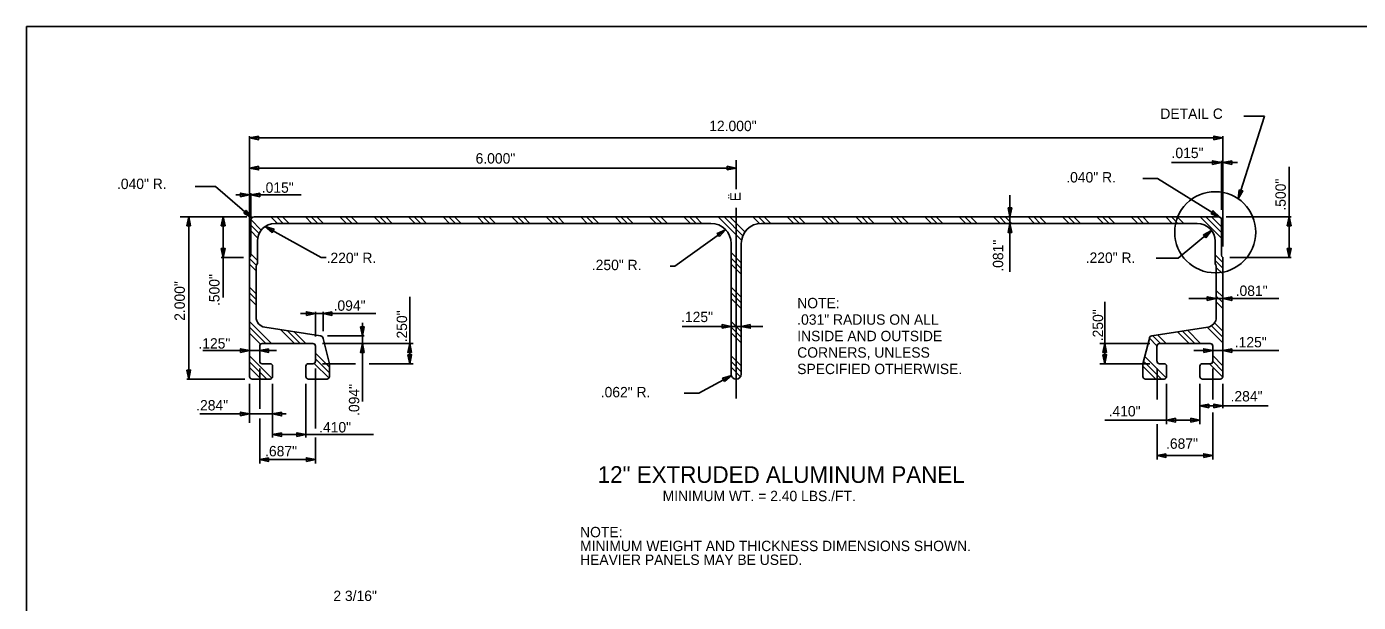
# Model space of a CAD drawing. Extents: x -439.1 to -407.9, y -458.1 to -437.7.
# Drawn here: x -439.11 to -419.86, y -446 to -437.68 of the extents above; entities that cross this region are included whole.
import ezdxf

# ---------------------------------------------------------------- set-up
doc = ezdxf.new("R2010")
doc.units = 0
for name, color, linetype in [('Draft_Named_Boundary', 7, 'Continuous'), ('Level 4', 7, 'Continuous'), ('Level 45', 7, 'Continuous')]:
    doc.layers.add(name, color=color, linetype=linetype)

msp = doc.modelspace()

# ---------------------------------------------------------------- linework, layer by layer
at = {"layer": 'Draft_Named_Boundary'}
msp.add_lwpolyline([(-439.109, -458.051), (-407.859, -458.051), (-407.859, -437.676), (-439.109, -437.676)], close=True, dxfattribs=at)
at = {"layer": 'Level 4'}
for p, q in [((-421.595, -440.165), (-421.215, -438.972)), ((-421.513, -438.972), (-421.215, -438.972)), ((-435.887, -441.017), (-435.887, -439.257)), ((-421.817, -439.284), (-435.887, -439.284)), ((-421.817, -440.855), (-421.817, -439.257)), ((-428.852, -440.024), (-428.852, -439.604)), ((-422.559, -439.641), (-421.608, -439.641)), ((-421.835, -440.322), (-421.835, -439.614)), ((-435.887, -439.72), (-428.852, -439.72)), ((-422.763, -439.87), (-422.972, -439.87)), ((-421.863, -440.428), (-422.763, -439.87)), ((-420.859, -439.7), (-420.859, -440.424)), ((-436.671, -439.984), (-436.378, -439.984)), ((-435.856, -440.439), (-436.378, -439.984)), ((-436.085, -440.107), (-435.143, -440.107)), ((-435.869, -440.431), (-435.869, -440.081)), ((-424.895, -441.218), (-424.895, -440.11)), ((-435.925, -440.424), (-436.889, -440.424)), ((-436.765, -442.769), (-436.765, -440.424)), ((-436.268, -440.424), (-436.268, -441.59)), ((-421.882, -440.424), (-435.822, -440.424)), ((-435.482, -440.519), (-435.577, -440.424)), ((-435.399, -440.519), (-435.494, -440.424)), ((-435.316, -440.519), (-435.411, -440.424)), ((-434.985, -440.519), (-435.08, -440.424)), ((-434.902, -440.519), (-434.997, -440.424)), ((-434.819, -440.519), (-434.914, -440.424)), ((-434.487, -440.519), (-434.582, -440.424)), ((-434.404, -440.519), (-434.499, -440.424)), ((-434.321, -440.519), (-434.416, -440.424)), ((-433.99, -440.519), (-434.085, -440.424)), ((-433.907, -440.519), (-434.002, -440.424)), ((-433.824, -440.519), (-433.919, -440.424)), ((-433.492, -440.519), (-433.587, -440.424)), ((-433.41, -440.519), (-433.505, -440.424)), ((-433.327, -440.519), (-433.422, -440.424)), ((-432.995, -440.519), (-433.09, -440.424)), ((-432.912, -440.519), (-433.007, -440.424)), ((-432.829, -440.519), (-432.924, -440.424)), ((-432.498, -440.519), (-432.593, -440.424)), ((-432.415, -440.519), (-432.51, -440.424)), ((-432.332, -440.519), (-432.427, -440.424)), ((-432, -440.519), (-432.095, -440.424)), ((-431.917, -440.519), (-432.012, -440.424)), ((-431.834, -440.519), (-431.929, -440.424)), ((-431.503, -440.519), (-431.598, -440.424)), ((-431.42, -440.519), (-431.515, -440.424)), ((-431.337, -440.519), (-431.432, -440.424)), ((-431.005, -440.519), (-431.1, -440.424)), ((-430.922, -440.519), (-431.017, -440.424)), ((-430.839, -440.519), (-430.934, -440.424)), ((-430.508, -440.519), (-430.603, -440.424)), ((-430.425, -440.519), (-430.52, -440.424)), ((-430.342, -440.519), (-430.437, -440.424)), ((-430.01, -440.519), (-430.105, -440.424)), ((-429.928, -440.519), (-430.022, -440.424)), ((-429.845, -440.519), (-429.94, -440.424)), ((-429.513, -440.519), (-429.608, -440.424)), ((-429.43, -440.519), (-429.525, -440.424)), ((-429.347, -440.519), (-429.442, -440.424)), ((-428.774, -440.76), (-429.111, -440.424)), ((-428.755, -440.697), (-429.028, -440.424)), ((-428.725, -440.643), (-428.945, -440.424)), ((-428.852, -443.05), (-428.852, -440.296)), ((-428.516, -440.521), (-428.613, -440.424)), ((-428.435, -440.519), (-428.53, -440.424)), ((-428.352, -440.519), (-428.447, -440.424)), ((-428.021, -440.519), (-428.116, -440.424)), ((-427.938, -440.519), (-428.033, -440.424)), ((-427.855, -440.519), (-427.95, -440.424)), ((-427.523, -440.519), (-427.618, -440.424)), ((-427.44, -440.519), (-427.535, -440.424)), ((-427.357, -440.519), (-427.452, -440.424)), ((-427.026, -440.519), (-427.121, -440.424)), ((-426.943, -440.519), (-427.038, -440.424)), ((-426.86, -440.519), (-426.955, -440.424)), ((-426.528, -440.519), (-426.623, -440.424)), ((-426.446, -440.519), (-426.54, -440.424)), ((-426.363, -440.519), (-426.458, -440.424)), ((-426.031, -440.519), (-426.126, -440.424)), ((-425.948, -440.519), (-426.043, -440.424)), ((-425.865, -440.519), (-425.96, -440.424)), ((-425.534, -440.519), (-425.629, -440.424)), ((-425.451, -440.519), (-425.546, -440.424)), ((-425.368, -440.519), (-425.463, -440.424)), ((-425.036, -440.519), (-425.131, -440.424)), ((-424.953, -440.519), (-425.048, -440.424)), ((-424.87, -440.519), (-424.965, -440.424)), ((-424.539, -440.519), (-424.634, -440.424)), ((-424.456, -440.519), (-424.551, -440.424)), ((-424.373, -440.519), (-424.468, -440.424)), ((-424.041, -440.519), (-424.136, -440.424)), ((-423.958, -440.519), (-424.053, -440.424)), ((-423.875, -440.519), (-423.97, -440.424)), ((-423.544, -440.519), (-423.639, -440.424)), ((-423.461, -440.519), (-423.556, -440.424)), ((-423.378, -440.519), (-423.473, -440.424)), ((-423.046, -440.519), (-423.141, -440.424)), ((-422.963, -440.519), (-423.058, -440.424)), ((-422.881, -440.519), (-422.976, -440.424)), ((-422.549, -440.519), (-422.644, -440.424)), ((-422.466, -440.519), (-422.561, -440.424)), ((-422.383, -440.519), (-422.478, -440.424)), ((-421.835, -440.735), (-422.147, -440.424)), ((-421.835, -440.652), (-422.064, -440.424)), ((-421.835, -440.57), (-421.981, -440.424)), ((-421.77, -440.424), (-420.832, -440.424)), ((-420.859, -440.424), (-420.859, -441.011)), ((-435.717, -440.615), (-435.869, -440.464)), ((-435.869, -440.98), (-435.869, -440.471)), ((-435.749, -440.666), (-435.869, -440.546)), ((-435.77, -440.729), (-435.869, -440.629)), ((-435.659, -440.563), (-434.851, -441.013)), ((-429.218, -440.519), (-435.516, -440.519)), ((-429.005, -440.612), (-429.738, -441.136)), ((-422.188, -440.519), (-428.485, -440.519)), ((-421.98, -440.624), (-422.462, -441.022)), ((-421.835, -440.98), (-421.835, -440.471)), ((-435.774, -441.105), (-435.774, -440.777)), ((-428.925, -442.696), (-428.925, -440.812)), ((-428.778, -442.696), (-428.778, -440.812)), ((-421.93, -441.105), (-421.93, -440.777)), ((-435.972, -441.011), (-436.295, -441.011)), ((-435.887, -442.732), (-435.887, -441.01)), ((-435.774, -441.056), (-435.869, -440.961)), ((-434.851, -441.013), (-434.778, -441.013)), ((-428.778, -441.088), (-428.925, -440.941)), ((-428.778, -441.171), (-428.925, -441.024)), ((-422.78, -441.022), (-422.462, -441.022)), ((-421.817, -441.085), (-421.93, -440.972)), ((-421.817, -442.732), (-421.817, -441.01)), ((-421.715, -441.011), (-420.832, -441.011)), ((-435.789, -441.124), (-435.887, -441.026)), ((-435.792, -441.204), (-435.887, -441.109)), ((-435.792, -441.874), (-435.792, -441.137)), ((-429.738, -441.136), (-429.809, -441.136)), ((-428.778, -441.254), (-428.925, -441.107)), ((-421.817, -441.167), (-421.93, -441.055)), ((-421.912, -441.874), (-421.912, -441.137)), ((-421.817, -441.25), (-421.912, -441.155)), ((-435.792, -441.536), (-435.887, -441.441)), ((-435.792, -441.618), (-435.887, -441.524)), ((-433.572, -441.579), (-433.572, -442.549)), ((-428.778, -441.585), (-428.925, -441.439)), ((-428.778, -441.668), (-428.925, -441.522)), ((-421.817, -441.582), (-421.912, -441.487)), ((-421.817, -441.665), (-421.912, -441.57)), ((-435.792, -441.701), (-435.887, -441.606)), ((-428.778, -441.751), (-428.925, -441.604)), ((-423.525, -441.653), (-423.525, -442.256)), ((-421.01, -441.607), (-422.307, -441.607)), ((-421.817, -441.748), (-421.912, -441.653)), ((-435.57, -442.255), (-435.887, -441.938)), ((-435.149, -441.823), (-434.063, -441.823)), ((-434.935, -442.153), (-434.935, -441.796)), ((-434.825, -442.079), (-434.825, -441.796)), ((-434.256, -443.095), (-434.256, -441.955)), ((-428.778, -442.083), (-428.925, -441.936)), ((-421.817, -442.079), (-421.939, -441.958)), ((-435.653, -442.255), (-435.887, -442.021)), ((-435.727, -442.264), (-435.887, -442.104)), ((-434.861, -442.145), (-435.668, -442.018)), ((-435.238, -442.255), (-435.439, -442.055)), ((-435.155, -442.255), (-435.34, -442.07)), ((-435.072, -442.255), (-435.242, -442.086)), ((-434.758, -442.146), (-434.229, -442.146)), ((-429.631, -442.008), (-428.469, -442.008)), ((-428.778, -442.166), (-428.925, -442.019)), ((-428.778, -442.248), (-428.925, -442.102)), ((-422.77, -442.288), (-422.879, -442.179)), ((-422.843, -442.145), (-422.036, -442.018)), ((-422.719, -442.255), (-422.831, -442.143)), ((-422.636, -442.255), (-422.76, -442.132)), ((-422.305, -442.255), (-422.473, -442.087)), ((-422.222, -442.255), (-422.401, -442.076)), ((-422.139, -442.255), (-422.33, -442.065)), ((-421.817, -442.245), (-422.043, -442.02)), ((-421.817, -442.162), (-421.982, -441.998)), ((-436.561, -442.358), (-435.499, -442.358)), ((-435.74, -442.512), (-435.74, -442.292)), ((-434.971, -442.255), (-435.704, -442.255)), ((-434.935, -442.512), (-434.935, -442.292)), ((-434.832, -442.256), (-433.52, -442.256)), ((-434.825, -442.181), (-434.731, -442.548)), ((-422.872, -442.256), (-423.598, -442.256)), ((-423.525, -442.256), (-423.525, -442.549)), ((-422.88, -442.181), (-422.974, -442.548)), ((-422.77, -442.512), (-422.77, -442.292)), ((-422.733, -442.255), (-422, -442.255)), ((-421.01, -442.358), (-422.235, -442.358)), ((-421.964, -442.512), (-421.964, -442.292)), ((-435.564, -442.758), (-435.887, -442.435)), ((-435.636, -442.769), (-435.887, -442.518)), ((-435.59, -442.548), (-435.704, -442.548)), ((-434.971, -442.548), (-435.037, -442.548)), ((-434.738, -442.755), (-434.951, -442.543)), ((-434.731, -442.597), (-434.935, -442.393)), ((-434.731, -442.68), (-434.935, -442.476)), ((-434.832, -442.549), (-434.354, -442.549)), ((-434.731, -442.732), (-434.731, -442.548)), ((-434.158, -442.549), (-433.52, -442.549)), ((-428.778, -442.58), (-428.925, -442.433)), ((-428.778, -442.663), (-428.925, -442.516)), ((-422.872, -442.549), (-423.598, -442.549)), ((-422.974, -442.732), (-422.974, -442.548)), ((-422.703, -442.769), (-422.963, -442.509)), ((-422.637, -442.752), (-422.946, -442.443)), ((-422.733, -442.548), (-422.668, -442.548)), ((-422.114, -442.548), (-422, -442.548)), ((-421.818, -442.742), (-422.012, -442.548)), ((-421.817, -442.577), (-421.964, -442.43)), ((-421.817, -442.66), (-421.964, -442.513)), ((-435.719, -442.769), (-435.887, -442.601)), ((-435.74, -442.615), (-435.74, -443.199)), ((-435.554, -442.732), (-435.554, -442.585)), ((-435.073, -442.732), (-435.073, -442.585)), ((-434.935, -442.615), (-434.935, -443.484)), ((-428.921, -442.72), (-429.392, -442.974)), ((-428.79, -442.735), (-428.925, -442.599)), ((-422.786, -442.769), (-422.974, -442.582)), ((-422.769, -442.615), (-422.769, -443.063)), ((-422.631, -442.732), (-422.631, -442.585)), ((-422.15, -442.732), (-422.15, -442.585)), ((-421.964, -442.615), (-421.964, -443.063)), ((-435.953, -442.769), (-436.792, -442.769)), ((-435.887, -442.836), (-435.887, -443.403)), ((-435.59, -442.769), (-435.851, -442.769)), ((-435.554, -442.836), (-435.554, -443.613)), ((-435.073, -442.836), (-435.073, -443.613)), ((-434.767, -442.769), (-435.037, -442.769)), ((-422.937, -442.769), (-422.668, -442.769)), ((-422.631, -442.836), (-422.631, -443.42)), ((-422.15, -442.836), (-422.15, -443.42)), ((-422.114, -442.769), (-421.854, -442.769)), ((-421.817, -442.836), (-421.817, -443.188)), ((-429.392, -442.974), (-429.605, -442.974)), ((-436.607, -443.274), (-435.359, -443.274)), ((-421.817, -443.157), (-422.15, -443.157)), ((-421.964, -443.254), (-421.964, -443.933)), ((-421.163, -443.157), (-421.817, -443.157)), ((-435.74, -443.337), (-435.74, -443.989)), ((-422.631, -443.363), (-423.523, -443.363)), ((-422.769, -443.42), (-422.769, -443.933)), ((-422.15, -443.363), (-422.631, -443.363)), ((-435.554, -443.572), (-434.096, -443.572)), ((-434.935, -443.613), (-434.935, -443.989)), ((-421.964, -443.874), (-422.769, -443.874)), ((-435.74, -443.933), (-434.935, -443.933))]:
    msp.add_line(p, q, dxfattribs=at)
for points in [[(-435.757, -439.257), (-435.887, -439.284), (-435.757, -439.311)], [(-421.947, -439.311), (-421.817, -439.284), (-421.947, -439.257)], [(-421.965, -439.668), (-421.835, -439.641), (-421.965, -439.614)], [(-421.688, -439.614), (-421.817, -439.641), (-421.688, -439.668)], [(-435.757, -439.693), (-435.887, -439.72), (-435.757, -439.746)], [(-428.982, -439.746), (-428.852, -439.72), (-428.982, -439.693)], [(-421.581, -440.033), (-421.595, -440.165), (-421.53, -440.049)], [(-436.017, -440.134), (-435.887, -440.107), (-436.017, -440.081)], [(-435.74, -440.081), (-435.869, -440.107), (-435.74, -440.134)], [(-436.738, -440.554), (-436.765, -440.424), (-436.792, -440.554)], [(-436.241, -440.554), (-436.268, -440.424), (-436.295, -440.554)], [(-435.971, -440.374), (-435.856, -440.439), (-435.936, -440.333)], [(-424.922, -440.295), (-424.895, -440.424), (-424.868, -440.295)], [(-421.988, -440.383), (-421.863, -440.428), (-421.959, -440.337)], [(-420.832, -440.554), (-420.859, -440.424), (-420.886, -440.554)], [(-435.533, -440.602), (-435.659, -440.563), (-435.559, -440.649)], [(-429.095, -440.709), (-429.005, -440.612), (-429.126, -440.665)], [(-424.868, -440.649), (-424.895, -440.519), (-424.922, -440.649)], [(-422.063, -440.727), (-421.98, -440.624), (-422.098, -440.686)], [(-436.295, -440.881), (-436.268, -441.011), (-436.241, -440.881)], [(-420.886, -440.881), (-420.859, -441.011), (-420.832, -440.881)], [(-422.042, -441.634), (-421.912, -441.607), (-422.042, -441.58)], [(-421.688, -441.58), (-421.817, -441.607), (-421.688, -441.634)], [(-435.065, -441.85), (-434.935, -441.823), (-435.065, -441.796)], [(-434.695, -441.796), (-434.825, -441.823), (-434.695, -441.85)], [(-429.055, -442.035), (-428.925, -442.008), (-429.055, -441.981)], [(-428.649, -441.981), (-428.779, -442.008), (-428.649, -442.035)], [(-434.283, -442.016), (-434.256, -442.146), (-434.229, -442.016)], [(-436.017, -442.385), (-435.887, -442.358), (-436.017, -442.331)], [(-435.611, -442.331), (-435.74, -442.358), (-435.611, -442.385)], [(-434.229, -442.385), (-434.256, -442.256), (-434.283, -442.385)], [(-433.545, -442.385), (-433.572, -442.256), (-433.599, -442.385)], [(-423.498, -442.385), (-423.525, -442.256), (-423.552, -442.385)], [(-422.094, -442.385), (-421.964, -442.358), (-422.094, -442.331)], [(-421.688, -442.331), (-421.817, -442.358), (-421.688, -442.385)], [(-433.599, -442.419), (-433.572, -442.549), (-433.545, -442.419)], [(-423.552, -442.419), (-423.525, -442.549), (-423.498, -442.419)], [(-436.792, -442.64), (-436.765, -442.769), (-436.738, -442.64)], [(-429.023, -442.806), (-428.921, -442.72), (-429.048, -442.758)], [(-422.021, -443.13), (-422.15, -443.157), (-422.021, -443.184)], [(-421.947, -443.184), (-421.817, -443.157), (-421.947, -443.13)], [(-436.017, -443.301), (-435.887, -443.274), (-436.017, -443.247)], [(-435.424, -443.247), (-435.554, -443.274), (-435.424, -443.301)], [(-422.501, -443.336), (-422.631, -443.363), (-422.501, -443.39)], [(-422.28, -443.39), (-422.15, -443.363), (-422.28, -443.336)], [(-435.424, -443.545), (-435.554, -443.572), (-435.424, -443.599)], [(-435.203, -443.599), (-435.073, -443.572), (-435.203, -443.545)], [(-435.611, -443.906), (-435.74, -443.933), (-435.611, -443.96)], [(-435.065, -443.96), (-434.935, -443.933), (-435.065, -443.906)], [(-422.64, -443.848), (-422.769, -443.874), (-422.64, -443.901)], [(-422.094, -443.901), (-421.964, -443.874), (-422.094, -443.848)]]:
    msp.add_lwpolyline(points, close=True, dxfattribs=at)
msp.add_circle((-421.927, -440.648), 0.586, dxfattribs=at)
for centre, radius, start, end in [((-435.822, -440.471), 0.0469, 90, 180), ((-421.882, -440.471), 0.0469, 0, 90), ((-435.516, -440.777), 0.258, 90, 180), ((-429.218, -440.812), 0.293, 0, 90), ((-428.486, -440.812), 0.293, 90, 180), ((-422.188, -440.777), 0.258, 0, 90), ((-435.906, -440.979), 0.0363, 301, 2.7101), ((-421.799, -440.979), 0.0363, 177.2899, 239), ((-435.756, -441.137), 0.0363, 120.983, 177.0065), ((-421.949, -441.137), 0.0363, 2.9935, 59), ((-435.645, -441.874), 0.147, 180, 261.0533), ((-422.059, -441.874), 0.147, 278.9467, 360), ((-434.861, -442.182), 0.0363, 0, 90), ((-422.843, -442.182), 0.0363, 90, 180), ((-435.704, -442.292), 0.0363, 90, 180), ((-434.971, -442.292), 0.0363, 0, 90), ((-422.733, -442.292), 0.0363, 90, 180), ((-422, -442.292), 0.0363, 0, 90), ((-435.704, -442.513), 0.0363, 180, 270), ((-435.59, -442.585), 0.0363, 0, 90), ((-435.037, -442.585), 0.0363, 90, 180), ((-434.971, -442.513), 0.0363, 270, 360), ((-422.733, -442.513), 0.0363, 180, 270), ((-422.667, -442.585), 0.0363, 0, 90), ((-422.114, -442.585), 0.0363, 90, 180), ((-422, -442.513), 0.0363, 270, 0), ((-435.85, -442.733), 0.0363, 180, 270), ((-435.59, -442.733), 0.0363, 270, 360), ((-435.037, -442.733), 0.0363, 180, 270), ((-434.767, -442.733), 0.0363, 270, 360), ((-428.853, -442.697), 0.0727, 180, 270), ((-428.852, -442.697), 0.0727, 270, 360), ((-422.937, -442.733), 0.0363, 180, 270), ((-422.667, -442.733), 0.0363, 270, 0), ((-422.114, -442.733), 0.0363, 180, 270), ((-421.854, -442.733), 0.0363, 270, 0)]:
    msp.add_arc(centre, radius, start, end, dxfattribs=at)

# ---------------------------------------------------------------- texts
msp.add_text('DETAIL C', height=0.15, dxfattribs=at).set_placement((-422.721, -439.009))
msp.add_text('Ë', height=0.15, rotation=90, dxfattribs=at).set_placement((-428.788, -440.2))
at = {"layer": 'Level 45'}
for s, height, p in [('12.000"', 0.15, (-429.242, -439.186)), ('.015"', 0.15, (-422.559, -439.576)), ('6.000"', 0.15, (-432.619, -439.655)), ('.040" R.', 0.15, (-424.081, -439.928)), ('.040" R.', 0.15, (-437.803, -440.023)), ('.015"', 0.15, (-435.71, -440.077)), ('.220" R.', 0.15, (-434.773, -441.093)), ('.220" R.', 0.15, (-423.8, -441.09)), ('.250" R.', 0.15, (-430.939, -441.195)), ('NOTE:', 0.15, (-427.97, -441.746)), ('.081"', 0.15, (-421.632, -441.568)), ('.094"', 0.15, (-434.672, -441.782)), ('.125"', 0.15, (-429.649, -441.946)), ('.031" RADIUS ON ALL', 0.15, (-427.97, -441.984)), ('.125"', 0.15, (-436.626, -442.329)), ('INSIDE AND OUTSIDE', 0.15, (-427.97, -442.222)), ('.125"', 0.15, (-421.645, -442.311)), ('CORNERS, UNLESS', 0.15, (-427.97, -442.46)), ('SPECIFIED OTHERWISE.', 0.15, (-427.97, -442.698)), ('.062" R.', 0.15, (-430.81, -443.033)), ('.284"', 0.15, (-421.706, -443.093)), ('.284"', 0.15, (-436.658, -443.223)), ('.410"', 0.15, (-423.469, -443.309)), ('.410"', 0.15, (-434.881, -443.541)), ('.687"', 0.15, (-422.639, -443.777)), ('.687"', 0.15, (-435.662, -443.886)), ('12" EXTRUDED ALUMINUM PANEL', 0.24167, (-430.854, -444.27)), ('MINIMUM WT. = 2.40 LBS./FT.', 0.15, (-429.915, -444.534)), ('NOTE:', 0.15, (-431.109, -445.056)), ('MINIMUM WEIGHT AND THICKNESS DIMENSIONS SHOWN.', 0.15, (-431.109, -445.256)), ('HEAVIER PANELS MAY BE USED.', 0.15, (-431.109, -445.456)), ('2 3/16"', 0.15, (-434.675, -445.977))]:
    msp.add_text(s, height=height, dxfattribs=at).set_placement(p)
for s, p in [('.500"', (-420.908, -440.335)), ('.081"', (-424.992, -441.218)), ('2.000"', (-436.822, -441.928)), ('.500"', (-436.321, -441.714)), ('.250"', (-433.61, -442.239)), ('.250"', (-423.549, -442.223)), ('.094"', (-434.301, -443.302))]:
    msp.add_text(s, height=0.15, rotation=90, dxfattribs=at).set_placement(p)

doc.saveas('drawing.dxf')
